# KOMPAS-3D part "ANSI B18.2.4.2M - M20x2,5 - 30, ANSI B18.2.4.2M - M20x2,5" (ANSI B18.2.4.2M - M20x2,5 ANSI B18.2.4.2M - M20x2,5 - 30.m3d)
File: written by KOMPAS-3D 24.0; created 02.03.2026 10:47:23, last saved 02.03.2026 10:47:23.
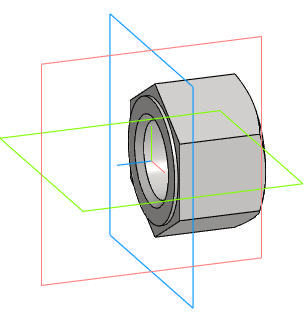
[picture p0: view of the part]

Document properties: Автор: R2D2; Полное имя файла: E:\Работа\Зайцев\GVWR3131M-2W-F-S Задвижка клиновая с выдвижным штоком DN.ru Ду50-200 Ру63\DN200\исходные материалы\ANSI B18.2.4.2M - M20x2,5 ANSI B18.2.4.2M - M20x2,5 - 30.m3d

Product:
- Body: Solid1  | qty 1
- Part/product: ANSI B18.2.4.2M - M20x2,5 - 30  | designation ANSI B18.2.4.2M - M20x2,5
    Комментарий: Типы метрических   шестигранных гаек   2
    additional columns: Сталь, мягкая

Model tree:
1. Solid1  (labels: Solid1)

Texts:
  ANSI B18.2.4.2M - M20x2,5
